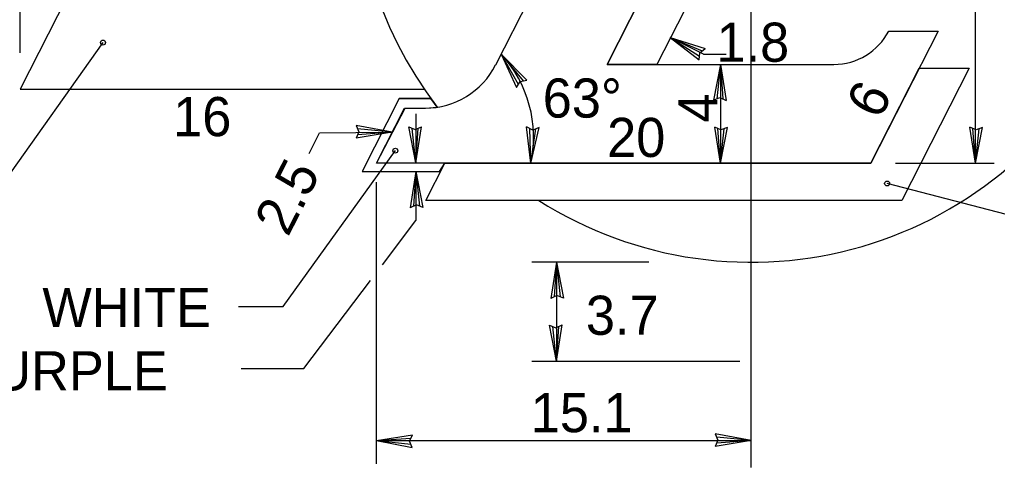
# Model space of a CAD drawing. Extents: x 10268197 to 10269179, y 2141503 to 2142677.
# Drawn here: x 10268467.86 to 10268485.36, y 2142117.75 to 2142125.76 of the extents above; entities that cross this region are included whole.
import ezdxf

# ---------------------------------------------------------------- set-up
doc = ezdxf.new("R2010")
doc.units = 0
for name, color, linetype in [('1', 7, 'Continuous'), ('2', 7, 'Continuous'), ('52', 7, 'Continuous'), ('SOILS_SP83_SHP', 7, 'Continuous')]:
    doc.layers.add(name, color=color, linetype=linetype)

msp = doc.modelspace()

# ---------------------------------------------------------------- linework, layer by layer
at = {"layer": '1'}
for p, q in [((10268480.958, 2142117.747), (10268480.958, 2142138.09)), ((10268467.878, 2142125.164), (10268467.878, 2142136.461)), ((10268484.969, 2142123.188), (10268484.969, 2142133.806)), ((10268478.376, 2142124.957), (10268479.841, 2142127.834)), ((10268480.396, 2142127.168), (10268479.269, 2142124.957)), ((10268467.601, 2142122.868), (10268469.358, 2142125.347)), ((10268480.101, 2142125.139), (10268479.509, 2142125.44)), ((10268480.101, 2142125.139), (10268480.508, 2142125.139)), ((10268479.269, 2142124.957), (10268478.376, 2142124.957)), ((10268480.406, 2142124.957), (10268480.406, 2142123.188)), ((10268483.097, 2142123.188), (10268483.964, 2142124.89)), ((10268484.858, 2142124.89), (10268483.653, 2142122.524)), ((10268483.964, 2142124.89), (10268484.858, 2142124.89)), ((10268474.957, 2142124.074), (10268474.957, 2142123.195)), ((10268473.044, 2142123.365), (10268473.233, 2142123.734)), ((10268473.233, 2142123.734), (10268474.533, 2142123.745)), ((10268472.582, 2142120.624), (10268474.589, 2142123.413)), ((10268475.134, 2142122.524), (10268475.472, 2142123.188)), ((10268475.472, 2142123.188), (10268483.097, 2142123.188)), ((10268483.54, 2142123.188), (10268485.301, 2142123.188)), ((10268474.957, 2142123.038), (10268474.957, 2142122.165)), ((10268474.249, 2142117.811), (10268474.249, 2142122.849)), ((10268485.66, 2142122.233), (10268483.388, 2142122.827)), ((10268483.653, 2142122.524), (10268475.134, 2142122.524)), ((10268474.357, 2142121.373), (10268474.957, 2142122.165)), ((10268479.125, 2142121.418), (10268477.03, 2142121.418)), ((10268477.472, 2142121.418), (10268477.472, 2142119.648)), ((10268472.952, 2142119.519), (10268474.144, 2142121.093)), ((10268471.781, 2142120.624), (10268472.582, 2142120.624)), ((10268471.828, 2142119.519), (10268472.952, 2142119.519)), ((10268477.03, 2142119.648), (10268480.75, 2142119.648)), ((10268474.249, 2142118.227), (10268480.958, 2142118.227))]:
    msp.add_line(p, q, dxfattribs=at)
msp.add_lwpolyline([(10268475.223, 2142124.346), (10268474.658, 2142124.346), (10268473.993, 2142123.038), (10268475.38, 2142123.038), (10268475.472, 2142123.188), (10268474.249, 2142123.188), (10268474.764, 2142124.173), (10268475.127, 2142124.173), (10268475.339, 2142124.19)], close=True, dxfattribs=at)
for centre in [(10268469.358, 2142125.346), (10268474.589, 2142123.412), (10268483.388, 2142122.826)]:
    msp.add_circle(centre, 0.0442, dxfattribs=at)
msp.add_arc((10268474.852, 2142123.646), 2.212, 348.03, 42.5026, dxfattribs=at)
at = {"layer": '2'}
for p, q in [((10268474.658, 2142124.346), (10268473.993, 2142123.038)), ((10268474.658, 2142124.346), (10268475.223, 2142124.346)), ((10268473.993, 2142123.038), (10268475.38, 2142123.038))]:
    msp.add_line(p, q, dxfattribs=at)
at = {"layer": '52'}
for p, q in [((10268479.509, 2142125.44), (10268480.132, 2142125.238)), ((10268479.509, 2142125.44), (10268480.026, 2142125.037)), ((10268479.509, 2142125.44), (10268480.031, 2142125.102)), ((10268479.509, 2142125.44), (10268480.081, 2142125.198)), ((10268476.483, 2142125.141), (10268476.942, 2142124.674)), ((10268476.483, 2142125.141), (10268476.755, 2142124.545)), ((10268476.483, 2142125.141), (10268476.789, 2142124.601)), ((10268476.483, 2142125.141), (10268476.878, 2142124.662)), ((10268480.026, 2142125.037), (10268480.036, 2142125.161)), ((10268480.036, 2142125.161), (10268480.132, 2142125.238)), ((10268480.406, 2142124.957), (10268480.28, 2142124.315)), ((10268480.406, 2142124.957), (10268480.341, 2142124.34)), ((10268480.406, 2142124.957), (10268480.508, 2142124.311)), ((10268480.406, 2142124.957), (10268480.449, 2142124.338)), ((10268476.755, 2142124.545), (10268476.82, 2142124.651)), ((10268476.82, 2142124.651), (10268476.942, 2142124.674)), ((10268480.28, 2142124.315), (10268480.395, 2142124.362)), ((10268480.395, 2142124.362), (10268480.508, 2142124.311)), ((10268473.937, 2142123.75), (10268473.887, 2142123.637)), ((10268474.533, 2142123.745), (10268473.887, 2142123.637)), ((10268474.533, 2142123.745), (10268473.889, 2142123.864)), ((10268473.889, 2142123.864), (10268473.937, 2142123.75)), ((10268474.533, 2142123.745), (10268473.914, 2142123.805)), ((10268474.533, 2142123.745), (10268473.914, 2142123.696)), ((10268474.957, 2142123.195), (10268474.832, 2142123.837)), ((10268474.832, 2142123.837), (10268474.946, 2142123.79)), ((10268474.957, 2142123.195), (10268474.892, 2142123.812)), ((10268474.946, 2142123.79), (10268475.059, 2142123.841)), ((10268474.957, 2142123.195), (10268475.059, 2142123.841)), ((10268474.957, 2142123.195), (10268475, 2142123.814)), ((10268477.016, 2142123.188), (10268476.936, 2142123.838)), ((10268477.047, 2142123.782), (10268476.936, 2142123.838)), ((10268477.016, 2142123.188), (10268476.995, 2142123.809)), ((10268477.016, 2142123.188), (10268477.163, 2142123.826)), ((10268477.016, 2142123.188), (10268477.102, 2142123.803)), ((10268477.163, 2142123.826), (10268477.047, 2142123.782)), ((10268480.406, 2142123.188), (10268480.303, 2142123.835)), ((10268480.415, 2142123.783), (10268480.303, 2142123.835)), ((10268480.406, 2142123.188), (10268480.362, 2142123.807)), ((10268480.406, 2142123.188), (10268480.53, 2142123.83)), ((10268480.406, 2142123.188), (10268480.47, 2142123.806)), ((10268480.53, 2142123.83), (10268480.415, 2142123.783)), ((10268484.969, 2142123.188), (10268484.866, 2142123.835)), ((10268484.979, 2142123.783), (10268484.866, 2142123.835)), ((10268484.969, 2142123.188), (10268484.925, 2142123.807)), ((10268484.969, 2142123.188), (10268485.093, 2142123.83)), ((10268484.969, 2142123.188), (10268485.033, 2142123.806)), ((10268485.093, 2142123.83), (10268484.979, 2142123.783)), ((10268474.957, 2142123.038), (10268474.854, 2142122.391)), ((10268474.957, 2142123.038), (10268474.913, 2142122.418)), ((10268474.957, 2142123.038), (10268475.081, 2142122.394)), ((10268474.957, 2142123.038), (10268475.021, 2142122.419)), ((10268474.967, 2142122.442), (10268474.854, 2142122.391)), ((10268475.081, 2142122.394), (10268474.967, 2142122.442)), ((10268477.472, 2142121.418), (10268477.369, 2142120.771)), ((10268477.472, 2142121.418), (10268477.428, 2142120.799)), ((10268477.472, 2142121.418), (10268477.596, 2142120.775)), ((10268477.472, 2142121.418), (10268477.536, 2142120.8)), ((10268477.481, 2142120.822), (10268477.369, 2142120.771)), ((10268477.596, 2142120.775), (10268477.481, 2142120.822)), ((10268477.472, 2142119.648), (10268477.347, 2142120.291)), ((10268477.347, 2142120.291), (10268477.462, 2142120.244)), ((10268477.472, 2142119.648), (10268477.407, 2142120.266)), ((10268477.462, 2142120.244), (10268477.575, 2142120.295)), ((10268477.472, 2142119.648), (10268477.575, 2142120.295)), ((10268477.472, 2142119.648), (10268477.515, 2142120.268)), ((10268474.249, 2142118.227), (10268474.896, 2142118.33)), ((10268474.249, 2142118.227), (10268474.868, 2142118.271)), ((10268474.844, 2142118.218), (10268474.896, 2142118.33)), ((10268480.958, 2142118.227), (10268480.313, 2142118.347)), ((10268480.313, 2142118.347), (10268480.362, 2142118.233)), ((10268480.958, 2142118.227), (10268480.339, 2142118.287)), ((10268474.249, 2142118.227), (10268474.892, 2142118.103)), ((10268474.249, 2142118.227), (10268474.867, 2142118.163)), ((10268474.892, 2142118.103), (10268474.844, 2142118.218)), ((10268480.362, 2142118.233), (10268480.312, 2142118.119)), ((10268480.958, 2142118.227), (10268480.312, 2142118.119)), ((10268480.958, 2142118.227), (10268480.339, 2142118.179))]:
    msp.add_line(p, q, dxfattribs=at)
at = {"layer": 'SOILS_SP83_SHP'}
for p, q in [((10268476.384, 2142124.946), (10268480.056, 2142132.153)), ((10268479.841, 2142127.834), (10268478.376, 2142124.957)), ((10268478.376, 2142124.957), (10268479.841, 2142127.834)), ((10268480.396, 2142127.168), (10268479.269, 2142124.957)), ((10268468.779, 2142126.285), (10268467.878, 2142124.515)), ((10268484.303, 2142125.553), (10268483.097, 2142123.188)), ((10268483.417, 2142125.553), (10268484.303, 2142125.553)), ((10268478.376, 2142124.957), (10268482.436, 2142124.957)), ((10268479.269, 2142124.957), (10268478.376, 2142124.957)), ((10268483.097, 2142123.188), (10268483.964, 2142124.89)), ((10268484.858, 2142124.89), (10268483.653, 2142122.524)), ((10268483.964, 2142124.89), (10268484.858, 2142124.89)), ((10268467.878, 2142124.515), (10268475.105, 2142124.515)), ((10268474.249, 2142123.188), (10268474.751, 2142124.173)), ((10268474.751, 2142124.173), (10268475.122, 2142124.173)), ((10268483.097, 2142123.188), (10268474.249, 2142123.188)), ((10268475.134, 2142122.524), (10268475.472, 2142123.188)), ((10268475.472, 2142123.188), (10268483.097, 2142123.188)), ((10268483.653, 2142122.524), (10268475.134, 2142122.524))]:
    msp.add_line(p, q, dxfattribs=at)
for centre, radius, start, end in [((10268480.957, 2142128.496), 7.079, 48.5904, 217.4727), ((10268480.957, 2142128.496), 7.079, 237.5383, 335.047), ((10268482.436, 2142126.063), 1.106, 270, 332.5096), ((10268475.122, 2142125.589), 1.416, 270, 332.9991)]:
    msp.add_arc(centre, radius, start, end, dxfattribs=at)

# ---------------------------------------------------------------- texts
at = {"layer": '1'}
for s, p in [('1.8', (10268480.335, 2142125.003)), ('63°', (10268477.226, 2142124.004)), ('16', (10268470.613, 2142123.672)), ('20', (10268478.378, 2142123.3)), ('WHITE', (10268468.273, 2142120.256)), ('3.7', (10268477.998, 2142120.119)), ('0.13" PURPLE', (10268464.357, 2142119.125)), ('15.1', (10268477.012, 2142118.377))]:
    msp.add_text(s, height=0.7, dxfattribs=at).set_placement(p)
for s, rotation, p in [('6', 63, (10268483.255, 2142123.947)), ('4', 90, (10268480.351, 2142123.915)), ('2.5', 63, (10268472.666, 2142121.854))]:
    msp.add_text(s, height=0.7, rotation=rotation, dxfattribs=at).set_placement(p)

doc.saveas('drawing.dxf')
